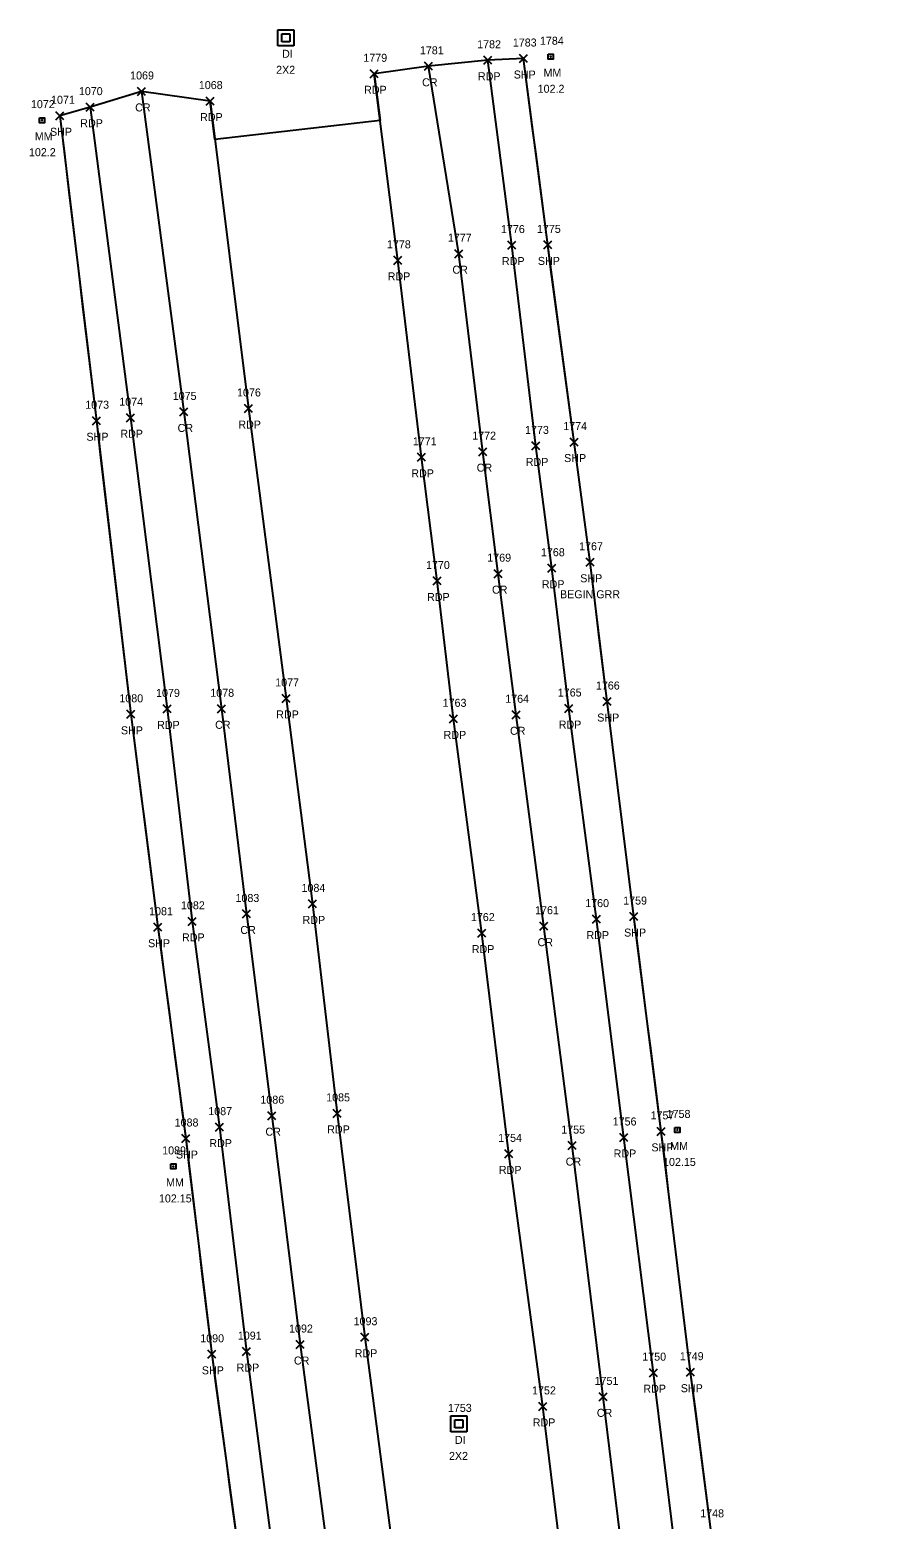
# Model space of a CAD drawing. Extents: x 1472022 to 1479249, y 777216 to 786527.
# Drawn here: x 1473808.2 to 1474023.2, y 782324.3 to 782696.6 of the extents above; entities that cross this region are included whole.
import ezdxf

# ---------------------------------------------------------------- set-up
doc = ezdxf.new("R2010")
doc.units = 0
for name, color, linetype in [('D_A', 7, 'Continuous'), ('D_C', 7, 'Continuous'), ('D_I', 7, 'Continuous'), ('DS', 7, 'Continuous'), ('LSOGP', 7, 'Continuous'), ('P_A', 7, 'Continuous'), ('P_C', 7, 'Continuous'), ('P_I', 7, 'Continuous'), ('P_TIC', 7, 'Continuous'), ('PET', 7, 'Continuous'), ('PRC', 7, 'Continuous'), ('PSP', 7, 'Continuous'), ('S_A', 7, 'Continuous'), ('S_C', 7, 'Continuous'), ('S_I', 7, 'Continuous'), ('SRM', 7, 'Continuous')]:
    doc.layers.add(name, color=color, linetype=linetype)

msp = doc.modelspace()

# ---------------------------------------------------------------- linework, layer by layer
at = {"layer": 'DS'}
for p, q in [((1473870.17, 782696.56), (1473874.17, 782696.56)), ((1473870.17, 782692.56), (1473870.17, 782696.56)), ((1473874.17, 782696.56), (1473874.17, 782692.56)), ((1473874.17, 782692.56), (1473870.17, 782692.56)), ((1473871.17, 782693.56), (1473871.17, 782695.56)), ((1473871.17, 782695.56), (1473873.17, 782695.56)), ((1473873.17, 782693.56), (1473871.17, 782693.56)), ((1473872.17, 782694.56), (1473872.17, 782694.56)), ((1473872.17, 782694.56), (1473872.17, 782694.56)), ((1473873.17, 782695.56), (1473873.17, 782693.56)), ((1473913.37, 782350.13), (1473917.37, 782350.13)), ((1473913.37, 782346.13), (1473913.37, 782350.13)), ((1473917.37, 782350.13), (1473917.37, 782346.13)), ((1473917.37, 782346.13), (1473913.37, 782346.13)), ((1473914.37, 782347.13), (1473914.37, 782349.13)), ((1473914.37, 782349.13), (1473916.37, 782349.13)), ((1473916.37, 782347.13), (1473914.37, 782347.13)), ((1473915.38, 782348.14), (1473915.38, 782348.14)), ((1473915.38, 782348.14), (1473915.38, 782348.14)), ((1473916.37, 782349.13), (1473916.37, 782347.13))]:
    msp.add_line(p, q, dxfattribs=at)
at = {"layer": 'LSOGP'}
msp.add_lwpolyline([(1473978.42, 782321.78), (1473977.15, 782331.6), (1473975.88, 782341.42), (1473974.61, 782351.24), (1473973.33, 782361.06), (1473972.42, 782368.58), (1473971.5, 782376.1), (1473970.59, 782383.63), (1473969.67, 782391.15), (1473968.76, 782398.68), (1473967.84, 782406.2), (1473966.93, 782413.73), (1473966.01, 782421.25), (1473965.16, 782427.96), (1473964.3, 782434.67), (1473963.45, 782441.38), (1473962.59, 782448.09), (1473961.74, 782454.8), (1473960.89, 782461.51), (1473960.03, 782468.22), (1473959.18, 782474.93), (1473958.34, 782481.64), (1473957.5, 782488.36), (1473956.66, 782495.08), (1473955.82, 782501.8), (1473954.98, 782508.51), (1473954.14, 782515.23), (1473953.3, 782521.95), (1473952.46, 782528.67), (1473951.39, 782537.37), (1473950.33, 782546.07), (1473949.27, 782554.78), (1473948.21, 782563.48), (1473947.2, 782570.99), (1473946.2, 782578.5), (1473945.2, 782586.01), (1473944.2, 782593.52), (1473943.37, 782599.68), (1473942.55, 782605.84), (1473941.73, 782612), (1473940.91, 782618.16), (1473940.09, 782624.32), (1473939.26, 782630.48), (1473938.44, 782636.64), (1473937.62, 782642.8), (1473936.87, 782648.62), (1473936.11, 782654.44), (1473935.36, 782660.27), (1473934.61, 782666.09), (1473933.85, 782671.91), (1473933.1, 782677.73), (1473932.35, 782683.56), (1473931.59, 782689.38), (1473922.69, 782688.94), (1473907.8, 782687.43), (1473894.25, 782685.56), (1473894.99, 782679.73), (1473895.72, 782673.9), (1473854.45, 782669.14), (1473853.26, 782678.74), (1473836.1, 782681.15), (1473823.32, 782677.22), (1473815.72, 782675.07), (1473816.85, 782665.54), (1473817.99, 782656.01), (1473819.13, 782646.49), (1473820.27, 782636.96), (1473821.41, 782627.43), (1473822.55, 782617.91), (1473823.69, 782608.38), (1473824.83, 782598.85), (1473825.9, 782589.68), (1473826.98, 782580.51), (1473828.05, 782571.34), (1473829.13, 782562.17), (1473830.21, 782553), (1473831.28, 782543.83), (1473832.36, 782534.66), (1473833.44, 782525.48), (1473834.28, 782518.83), (1473835.13, 782512.18), (1473835.98, 782505.53), (1473836.83, 782498.88), (1473837.67, 782492.23), (1473838.52, 782485.58), (1473839.37, 782478.92), (1473840.22, 782472.27), (1473841.08, 782465.67), (1473841.95, 782459.07), (1473842.82, 782452.47), (1473843.69, 782445.87), (1473844.56, 782439.26), (1473845.43, 782432.66), (1473846.3, 782426.06), (1473847.17, 782419.46), (1473847.98, 782412.72), (1473848.79, 782405.98), (1473849.6, 782399.23), (1473850.41, 782392.49), (1473851.22, 782385.75), (1473852.03, 782379.01), (1473852.84, 782372.27), (1473853.65, 782365.53), (1473854.55, 782358.89), (1473855.45, 782352.25), (1473856.34, 782345.61), (1473857.24, 782338.98), (1473858.14, 782332.34), (1473859.03, 782325.7), (1473859.93, 782319.06)], dxfattribs=at)
at = {"layer": 'P_TIC'}
for points in [[(1473906.8, 782686.43), (1473908.8, 782688.43)], [(1473908.8, 782686.43), (1473906.8, 782688.43)], [(1473921.69, 782687.94), (1473923.69, 782689.94)], [(1473923.69, 782687.94), (1473921.69, 782689.94)], [(1473930.59, 782688.38), (1473932.59, 782690.38)], [(1473932.59, 782688.38), (1473930.59, 782690.38)], [(1473893.25, 782684.56), (1473895.25, 782686.56)], [(1473895.25, 782684.56), (1473893.25, 782686.56)], [(1473835.1, 782680.15), (1473837.1, 782682.15)], [(1473837.1, 782680.15), (1473835.1, 782682.15)], [(1473822.32, 782676.22), (1473824.32, 782678.22)], [(1473824.32, 782676.22), (1473822.32, 782678.22)], [(1473852.26, 782677.74), (1473854.26, 782679.74)], [(1473854.26, 782677.74), (1473852.26, 782679.74)], [(1473814.72, 782674.07), (1473816.72, 782676.07)], [(1473816.72, 782674.07), (1473814.72, 782676.07)], [(1473927.69, 782641.75), (1473929.69, 782643.75)], [(1473929.69, 782641.75), (1473927.69, 782643.75)], [(1473936.62, 782641.8), (1473938.62, 782643.8)], [(1473938.62, 782641.8), (1473936.62, 782643.8)], [(1473899.14, 782637.94), (1473901.14, 782639.94)], [(1473901.14, 782637.94), (1473899.14, 782639.94)], [(1473914.37, 782639.6), (1473916.37, 782641.6)], [(1473916.37, 782639.6), (1473914.37, 782641.6)], [(1473861.81, 782600.91), (1473863.81, 782602.91)], [(1473863.81, 782600.91), (1473861.81, 782602.91)], [(1473823.83, 782597.85), (1473825.83, 782599.85)], [(1473825.83, 782597.85), (1473823.83, 782599.85)], [(1473832.33, 782598.61), (1473834.33, 782600.61)], [(1473834.33, 782598.61), (1473832.33, 782600.61)], [(1473845.69, 782600.05), (1473847.69, 782602.05)], [(1473847.69, 782600.05), (1473845.69, 782602.05)], [(1473920.44, 782590.12), (1473922.44, 782592.12)], [(1473922.44, 782590.12), (1473920.44, 782592.12)], [(1473933.65, 782591.56), (1473935.65, 782593.56)], [(1473935.65, 782591.56), (1473933.65, 782593.56)], [(1473943.2, 782592.52), (1473945.2, 782594.52)], [(1473945.2, 782592.52), (1473943.2, 782594.52)], [(1473905.05, 782588.71), (1473907.05, 782590.71)], [(1473907.05, 782588.71), (1473905.05, 782590.71)], [(1473924.27, 782559.63), (1473926.27, 782561.63)], [(1473926.27, 782559.63), (1473924.27, 782561.63)], [(1473937.67, 782560.99), (1473939.67, 782562.99)], [(1473939.67, 782560.99), (1473937.67, 782562.99)], [(1473947.21, 782562.48), (1473949.21, 782564.48)], [(1473949.21, 782562.48), (1473947.21, 782564.48)], [(1473908.99, 782557.8), (1473910.99, 782559.8)], [(1473910.99, 782557.8), (1473908.99, 782559.8)], [(1473871.29, 782528.45), (1473873.29, 782530.45)], [(1473873.29, 782528.45), (1473871.29, 782530.45)], [(1473951.46, 782527.67), (1473953.46, 782529.67)], [(1473953.46, 782527.67), (1473951.46, 782529.67)], [(1473832.44, 782524.48), (1473834.44, 782526.48)], [(1473834.44, 782524.48), (1473832.44, 782526.48)], [(1473841.53, 782525.83), (1473843.53, 782527.83)], [(1473843.53, 782525.83), (1473841.53, 782527.83)], [(1473855.08, 782525.86), (1473857.08, 782527.86)], [(1473857.08, 782525.86), (1473855.08, 782527.86)], [(1473913.11, 782523.35), (1473915.11, 782525.35)], [(1473915.11, 782523.35), (1473913.11, 782525.35)], [(1473928.75, 782524.36), (1473930.75, 782526.36)], [(1473930.75, 782524.36), (1473928.75, 782526.36)], [(1473941.88, 782525.93), (1473943.88, 782527.93)], [(1473943.88, 782525.93), (1473941.88, 782527.93)], [(1473861.37, 782474.58), (1473863.37, 782476.58)], [(1473863.37, 782474.58), (1473861.37, 782476.58)], [(1473877.87, 782477.11), (1473879.87, 782479.11)], [(1473879.87, 782477.11), (1473877.87, 782479.11)], [(1473839.22, 782471.27), (1473841.22, 782473.27)], [(1473841.22, 782471.27), (1473839.22, 782473.27)], [(1473847.75, 782472.74), (1473849.75, 782474.74)], [(1473849.75, 782472.74), (1473847.75, 782474.74)], [(1473935.64, 782471.53), (1473937.64, 782473.53)], [(1473937.64, 782471.53), (1473935.64, 782473.53)], [(1473948.82, 782473.29), (1473950.82, 782475.29)], [(1473950.82, 782473.29), (1473948.82, 782475.29)], [(1473958.18, 782473.93), (1473960.18, 782475.93)], [(1473960.18, 782473.93), (1473958.18, 782475.93)], [(1473920.17, 782469.8), (1473922.17, 782471.8)], [(1473922.17, 782469.8), (1473920.17, 782471.8)], [(1473867.64, 782424.17), (1473869.64, 782426.17)], [(1473869.64, 782424.17), (1473867.64, 782426.17)], [(1473884.04, 782424.74), (1473886.04, 782426.74)], [(1473886.04, 782424.74), (1473884.04, 782426.74)], [(1473846.17, 782418.46), (1473848.17, 782420.46)], [(1473848.17, 782418.46), (1473846.17, 782420.46)], [(1473854.58, 782421.3), (1473856.58, 782423.3)], [(1473856.58, 782421.3), (1473854.58, 782423.3)], [(1473955.61, 782418.72), (1473957.61, 782420.72)], [(1473957.61, 782418.72), (1473955.61, 782420.72)], [(1473965.01, 782420.25), (1473967.01, 782422.25)], [(1473967.01, 782420.25), (1473965.01, 782422.25)], [(1473926.93, 782414.63), (1473928.93, 782416.63)], [(1473928.93, 782414.63), (1473926.93, 782416.63)], [(1473942.69, 782416.69), (1473944.69, 782418.69)], [(1473944.69, 782416.69), (1473942.69, 782418.69)], [(1473874.77, 782366.97), (1473876.77, 782368.97)], [(1473876.77, 782366.97), (1473874.77, 782368.97)], [(1473890.89, 782368.8), (1473892.89, 782370.8)], [(1473892.89, 782368.8), (1473890.89, 782370.8)], [(1473852.65, 782364.53), (1473854.65, 782366.53)], [(1473854.65, 782364.53), (1473852.65, 782366.53)], [(1473861.39, 782365.21), (1473863.39, 782367.21)], [(1473863.39, 782365.21), (1473861.39, 782367.21)], [(1473963.03, 782359.94), (1473965.03, 782361.94)], [(1473965.03, 782359.94), (1473963.03, 782361.94)], [(1473972.33, 782360.06), (1473974.33, 782362.06)], [(1473974.33, 782360.06), (1473972.33, 782362.06)], [(1473935.4, 782351.51), (1473937.4, 782353.51)], [(1473937.4, 782351.51), (1473935.4, 782353.51)], [(1473950.46, 782353.9), (1473952.46, 782355.9)], [(1473952.46, 782353.9), (1473950.46, 782355.9)]]:
    msp.add_lwpolyline(points, dxfattribs=at)
at = {"layer": 'PET'}
for points in [[(1474013.69, 781892.18), (1474009.96, 781943.03), (1474006.04, 781995.15), (1474000.49, 782052.02), (1473996.08, 782094.84), (1473991.19, 782137.97), (1473985.56, 782186.94), (1473979.75, 782232.63), (1473974.58, 782277.36), (1473969.2, 782318.89), (1473964.03, 782360.94), (1473956.61, 782419.72), (1473949.82, 782474.29), (1473942.88, 782526.93), (1473938.67, 782561.99), (1473934.65, 782592.56), (1473928.69, 782642.75), (1473922.69, 782688.94)], [(1473985.44, 781889.72), (1473981.98, 781941.8), (1473978.08, 781993.88), (1473972.71, 782048.23), (1473968.17, 782091.71), (1473963.4, 782135.69), (1473957.31, 782184.57), (1473951.51, 782230.2), (1473946.14, 782274.71), (1473941.19, 782313.76), (1473936.4, 782352.51), (1473927.93, 782415.63), (1473921.17, 782470.8), (1473914.11, 782524.35), (1473909.99, 782558.8), (1473906.05, 782589.71), (1473900.14, 782638.94), (1473894.25, 782685.56)], [(1473823.32, 782677.22), (1473833.33, 782599.61), (1473842.53, 782526.83), (1473848.75, 782473.74), (1473855.58, 782422.3), (1473862.39, 782366.21), (1473869.18, 782313.85), (1473875.71, 782258.2), (1473882.8, 782203.94), (1473889.42, 782149.71), (1473895.62, 782095.5), (1473901.27, 782040.19), (1473906.73, 781982.64), (1473911.24, 781925.62)], [(1473853.26, 782678.74), (1473862.81, 782601.91), (1473872.29, 782529.45), (1473878.87, 782478.11), (1473885.04, 782425.74), (1473891.89, 782369.8), (1473898.9, 782316.38), (1473905.27, 782261.68), (1473912.06, 782207.53), (1473918.55, 782154.32), (1473925.4, 782097.13), (1473931.1, 782043.01), (1473936.65, 781984.46), (1473941.26, 781927.31)]]:
    msp.add_lwpolyline(points, dxfattribs=at)
at = {"layer": 'PRC'}
for points in [[(1474000.48, 781890.51), (1473996.64, 781942.33), (1473992.75, 781993.73), (1473987.41, 782050.11), (1473982.69, 782092.94), (1473977.75, 782136.74), (1473972.62, 782185.34), (1473966.37, 782231.63), (1473961.16, 782276.18), (1473956.15, 782316.84), (1473951.46, 782354.9), (1473943.69, 782417.69), (1473936.64, 782472.53), (1473929.75, 782525.36), (1473925.27, 782560.63), (1473921.44, 782591.12), (1473915.37, 782640.6), (1473907.8, 782687.43)], [(1473836.1, 782681.15), (1473846.69, 782601.05), (1473856.08, 782526.86), (1473862.37, 782475.58), (1473868.64, 782425.17), (1473875.77, 782367.97), (1473882.76, 782314.97), (1473889.35, 782259.54), (1473896.33, 782205.24), (1473902.66, 782152.32), (1473909.3, 782096.74), (1473914.5, 782041.75), (1473920.36, 781983.62), (1473924.52, 781926.3)]]:
    msp.add_lwpolyline(points, dxfattribs=at)
at = {"layer": 'PSP'}
for points in [[(1474023.21, 781893.51), (1474019.96, 781943.82), (1474015.51, 781996.53), (1474014.23, 782008.91), (1474009.76, 782053.22), (1474005.41, 782096.71), (1474000.42, 782139.1), (1473994.67, 782187.68), (1473988.77, 782234.07), (1473983.65, 782278.85), (1473978.42, 782321.78), (1473973.33, 782361.06), (1473966.01, 782421.25), (1473959.18, 782474.93), (1473952.46, 782528.67), (1473948.21, 782563.48), (1473944.2, 782593.52), (1473937.62, 782642.8), (1473931.59, 782689.38)], [(1473815.72, 782675.07), (1473824.83, 782598.85), (1473833.44, 782525.48), (1473840.22, 782472.27), (1473847.17, 782419.46), (1473853.65, 782365.53), (1473860.83, 782312.43), (1473867.42, 782257.22), (1473874.03, 782203.74), (1473881.37, 782148.92), (1473888.32, 782094.71), (1473894.18, 782041.01), (1473899.44, 781982.31), (1473904.16, 781925.33)]]:
    msp.add_lwpolyline(points, dxfattribs=at)
at = {"layer": 'SRM'}
for points in [[(1473937.74, 782690.45), (1473938.99, 782690.45), (1473938.99, 782689.2), (1473937.74, 782689.2)], [(1473810.63, 782674.59), (1473811.88, 782674.59), (1473811.88, 782673.34), (1473810.63, 782673.34)], [(1473969.41, 782422.23), (1473970.66, 782422.23), (1473970.66, 782420.98), (1473969.41, 782420.98)], [(1473843.44, 782413.12), (1473844.69, 782413.12), (1473844.69, 782411.87), (1473843.44, 782411.87)]]:
    msp.add_lwpolyline(points, close=True, dxfattribs=at)
for centre in [(1473938.37, 782689.82), (1473811.25, 782673.97), (1473970.03, 782421.61), (1473844.06, 782412.49)]:
    msp.add_circle(centre, 0.0833, dxfattribs=at)

# ---------------------------------------------------------------- texts
at = {"layer": 'D_A'}
for p in [(1473871.23, 782689.56), (1473914.43, 782343.14)]:
    msp.add_text('DI', height=2, dxfattribs=at).set_placement(p)
at = {"layer": 'D_C'}
for p in [(1473869.75, 782685.56), (1473912.95, 782339.14)]:
    msp.add_text('2X2', height=2, dxfattribs=at).set_placement(p)
at = {"layer": 'D_I'}
msp.add_text('1753', height=2, dxfattribs=at).set_placement((1473912.68, 782351.14))
at = {"layer": 'P_A'}
for s, p in [('RDP', (1473920.18, 782683.94)), ('SHP', (1473929.13, 782684.38)), ('RDP', (1473891.74, 782680.56)), ('CR', (1473906.23, 782682.43)), ('CR', (1473834.53, 782676.15)), ('RDP', (1473820.81, 782672.22)), ('RDP', (1473850.75, 782673.74)), ('SHP', (1473813.25, 782670.07)), ('SHP', (1473935.16, 782637.8)), ('CR', (1473913.8, 782635.6)), ('RDP', (1473926.18, 782637.75)), ('RDP', (1473897.63, 782633.94)), ('RDP', (1473860.3, 782596.91)), ('SHP', (1473822.36, 782593.85)), ('RDP', (1473830.82, 782594.61)), ('CR', (1473845.13, 782596.05)), ('CR', (1473919.87, 782586.12)), ('RDP', (1473932.14, 782587.56)), ('SHP', (1473941.73, 782588.52)), ('RDP', (1473903.53, 782584.71)), ('RDP', (1473936.16, 782556.99)), ('SHP', (1473945.74, 782558.48)), ('RDP', (1473907.47, 782553.8)), ('CR', (1473923.7, 782555.63)), ('RDP', (1473869.78, 782524.45)), ('SHP', (1473949.99, 782523.67)), ('SHP', (1473830.97, 782520.48)), ('RDP', (1473840.02, 782521.83)), ('CR', (1473854.51, 782521.86)), ('RDP', (1473911.6, 782519.35)), ('CR', (1473928.19, 782520.36)), ('RDP', (1473940.37, 782521.93)), ('CR', (1473860.81, 782470.58)), ('RDP', (1473876.36, 782473.11)), ('SHP', (1473837.75, 782467.27)), ('RDP', (1473846.24, 782468.74)), ('CR', (1473935.08, 782467.53)), ('RDP', (1473947.31, 782469.29)), ('SHP', (1473956.71, 782469.93)), ('RDP', (1473918.65, 782465.8)), ('CR', (1473867.08, 782420.17)), ('RDP', (1473882.52, 782420.74)), ('SHP', (1473844.71, 782414.46)), ('RDP', (1473853.06, 782417.3)), ('RDP', (1473954.09, 782414.72)), ('SHP', (1473963.54, 782416.25)), ('CR', (1473942.12, 782412.69)), ('RDP', (1473925.42, 782410.63)), ('CR', (1473874.2, 782362.97)), ('RDP', (1473889.38, 782364.8)), ('SHP', (1473851.19, 782360.53)), ('RDP', (1473859.88, 782361.21)), ('RDP', (1473961.52, 782355.94)), ('SHP', (1473970.87, 782356.06)), ('RDP', (1473933.89, 782347.51)), ('CR', (1473949.89, 782349.9))]:
    msp.add_text(s, height=2, dxfattribs=at).set_placement(p)
at = {"layer": 'P_C'}
msp.add_text('BEGIN GRR', height=2, dxfattribs=at).set_placement((1473940.69, 782554.48))
at = {"layer": 'P_I'}
for s, p in [('1781', (1473905.68, 782690.43)), ('1782', (1473919.99, 782691.94)), ('1783', (1473928.9, 782692.38)), ('1779', (1473891.55, 782688.56)), ('1069', (1473833.27, 782684.15)), ('1070', (1473820.46, 782680.22)), ('1068', (1473850.44, 782681.74)), ('1071', (1473813.51, 782678.07)), ('1776', (1473925.94, 782645.75)), ('1775', (1473934.93, 782645.8)), ('1778', (1473897.45, 782641.94)), ('1777', (1473912.67, 782643.6)), ('1076', (1473859.99, 782604.91)), ('1073', (1473822.05, 782601.85)), ('1074', (1473830.56, 782602.61)), ('1075', (1473843.92, 782604.05)), ('1772', (1473918.75, 782594.12)), ('1773', (1473931.96, 782595.56)), ('1774', (1473941.5, 782596.52)), ('1771', (1473903.92, 782592.71)), ('1769', (1473922.52, 782563.63)), ('1768', (1473935.93, 782564.99)), ('1767', (1473945.47, 782566.48)), ('1770', (1473907.21, 782561.8)), ('1079', (1473839.75, 782529.83)), ('1078', (1473853.31, 782529.86)), ('1077', (1473869.52, 782532.45)), ('1765', (1473940.14, 782529.93)), ('1766', (1473949.66, 782531.67)), ('1080', (1473830.58, 782528.48)), ('1763', (1473911.37, 782527.35)), ('1764', (1473927.01, 782528.36)), ('1083', (1473859.6, 782478.58)), ('1084', (1473876.1, 782481.11)), ('1759', (1473956.48, 782477.93)), ('1081', (1473838.01, 782475.27)), ('1082', (1473845.98, 782476.74)), ('1761', (1473934.47, 782475.53)), ('1760', (1473946.99, 782477.29)), ('1762', (1473918.43, 782473.8)), ('1086', (1473865.82, 782428.17)), ('1085', (1473882.26, 782428.74)), ('1088', (1473844.4, 782422.46)), ('1087', (1473852.8, 782425.3)), ('1756', (1473953.86, 782422.72)), ('1757', (1473963.32, 782424.25)), ('1754', (1473925.24, 782418.63)), ('1755', (1473941, 782420.69)), ('1092', (1473872.99, 782370.97)), ('1093', (1473889.12, 782372.8)), ('1090', (1473850.79, 782368.53)), ('1091', (1473860.19, 782369.21)), ('1750', (1473961.25, 782363.94)), ('1749', (1473970.63, 782364.06)), ('1752', (1473933.71, 782355.51)), ('1751', (1473949.33, 782357.9)), ('1748', (1473975.73, 782324.78))]:
    msp.add_text(s, height=2, dxfattribs=at).set_placement(p)
at = {"layer": 'S_A'}
for p in [(1473936.56, 782684.82), (1473809.44, 782668.97), (1473968.22, 782416.61), (1473842.25, 782407.49)]:
    msp.add_text('MM', height=2, dxfattribs=at).set_placement(p)
at = {"layer": 'S_C'}
for s, p in [('102.2', (1473935.11, 782680.82)), ('102.2', (1473807.99, 782664.97)), ('102.15', (1473966.44, 782412.61)), ('102.15', (1473840.47, 782403.49))]:
    msp.add_text(s, height=2, dxfattribs=at).set_placement(p)
at = {"layer": 'S_I'}
for s, p in [('1784', (1473935.68, 782692.82)), ('1072', (1473808.48, 782676.97)), ('1758', (1473967.34, 782424.61)), ('1089', (1473841.28, 782415.49))]:
    msp.add_text(s, height=2, dxfattribs=at).set_placement(p)

doc.saveas('drawing.dxf')
